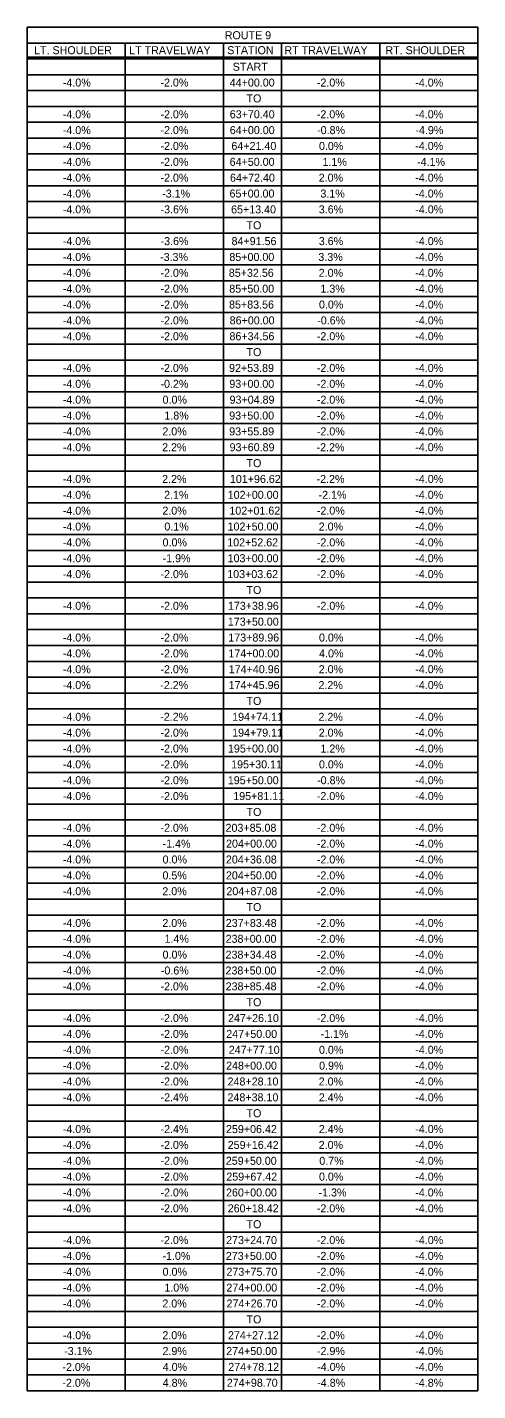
# Model space of a CAD drawing. Extents: x -15318841 to 1762012, y 465773 to 3693661.
# Drawn here: x -15318841 to -15318672, y 3691464 to 3691975 of the extents above; entities that cross this region are included whole.
import ezdxf

# ---------------------------------------------------------------- set-up
doc = ezdxf.new("R2010")
doc.units = 0
doc.layers.add('BORDER', color=7, linetype='Continuous')
doc.layers.add('DIMENSIONS', color=7, linetype='Continuous')

msp = doc.modelspace()

# ---------------------------------------------------------------- linework, layer by layer
at = {"layer": 'BORDER'}
for p, q in [((-15318803.96, 3691969.22), (-15318803.96, 3691464.16)), ((-15318767.19, 3691969.22), (-15318767.19, 3691464.16)), ((-15318745.32, 3691969.22), (-15318745.32, 3691464.16)), ((-15318708.55, 3691969.22), (-15318708.55, 3691464.16)), ((-15318840.73, 3691963.94), (-15318671.78, 3691963.94)), ((-15318840.73, 3691963.35), (-15318671.78, 3691963.35)), ((-15318840.73, 3691957.4), (-15318671.78, 3691957.4)), ((-15318840.73, 3691957.4), (-15318671.78, 3691957.4)), ((-15318840.73, 3691957.4), (-15318671.78, 3691957.4)), ((-15318840.73, 3691951.46), (-15318671.78, 3691951.46)), ((-15318840.73, 3691945.52), (-15318671.78, 3691945.52)), ((-15318840.73, 3691939.58), (-15318671.78, 3691939.58)), ((-15318840.73, 3691933.63), (-15318671.78, 3691933.63)), ((-15318840.73, 3691927.69), (-15318671.78, 3691927.69)), ((-15318840.73, 3691921.75), (-15318671.78, 3691921.75)), ((-15318840.73, 3691915.8), (-15318671.78, 3691915.8)), ((-15318840.73, 3691909.86), (-15318671.78, 3691909.86)), ((-15318840.73, 3691903.92), (-15318671.78, 3691903.92)), ((-15318840.73, 3691897.98), (-15318671.78, 3691897.98)), ((-15318840.73, 3691892.03), (-15318671.78, 3691892.03)), ((-15318840.73, 3691886.09), (-15318671.78, 3691886.09)), ((-15318840.73, 3691880.15), (-15318671.78, 3691880.15)), ((-15318840.73, 3691874.21), (-15318671.78, 3691874.21)), ((-15318840.73, 3691868.26), (-15318671.78, 3691868.26)), ((-15318840.73, 3691862.32), (-15318671.78, 3691862.32)), ((-15318840.73, 3691856.38), (-15318671.78, 3691856.38)), ((-15318840.73, 3691850.43), (-15318671.78, 3691850.43)), ((-15318840.73, 3691844.49), (-15318671.78, 3691844.49)), ((-15318840.73, 3691838.55), (-15318671.78, 3691838.55)), ((-15318840.73, 3691832.61), (-15318671.78, 3691832.61)), ((-15318840.73, 3691826.66), (-15318671.78, 3691826.66)), ((-15318840.73, 3691820.72), (-15318671.78, 3691820.72)), ((-15318840.73, 3691814.78), (-15318671.78, 3691814.78)), ((-15318840.73, 3691808.84), (-15318671.78, 3691808.84)), ((-15318840.73, 3691802.89), (-15318671.78, 3691802.89)), ((-15318840.73, 3691796.95), (-15318671.78, 3691796.95)), ((-15318840.73, 3691791.01), (-15318671.78, 3691791.01)), ((-15318840.73, 3691785.07), (-15318671.78, 3691785.07)), ((-15318840.73, 3691779.12), (-15318671.78, 3691779.12)), ((-15318840.73, 3691773.18), (-15318671.78, 3691773.18)), ((-15318840.73, 3691767.24), (-15318671.78, 3691767.24)), ((-15318840.73, 3691761.29), (-15318671.78, 3691761.29)), ((-15318840.73, 3691755.35), (-15318671.78, 3691755.35)), ((-15318840.73, 3691749.41), (-15318671.78, 3691749.41)), ((-15318840.73, 3691743.47), (-15318671.78, 3691743.47)), ((-15318840.73, 3691737.52), (-15318671.78, 3691737.52)), ((-15318840.73, 3691731.58), (-15318671.78, 3691731.58)), ((-15318840.73, 3691725.64), (-15318671.78, 3691725.64)), ((-15318840.73, 3691719.7), (-15318671.78, 3691719.7)), ((-15318840.73, 3691713.75), (-15318671.78, 3691713.75)), ((-15318840.73, 3691707.81), (-15318671.78, 3691707.81)), ((-15318840.73, 3691701.87), (-15318671.78, 3691701.87)), ((-15318840.73, 3691695.92), (-15318671.78, 3691695.92)), ((-15318840.73, 3691689.98), (-15318671.78, 3691689.98)), ((-15318840.73, 3691684.04), (-15318671.78, 3691684.04)), ((-15318840.73, 3691678.1), (-15318671.78, 3691678.1)), ((-15318840.73, 3691672.15), (-15318671.78, 3691672.15)), ((-15318840.73, 3691666.21), (-15318671.78, 3691666.21)), ((-15318840.73, 3691660.27), (-15318671.78, 3691660.27)), ((-15318840.73, 3691654.33), (-15318671.78, 3691654.33)), ((-15318840.73, 3691648.38), (-15318671.78, 3691648.38)), ((-15318840.73, 3691642.44), (-15318671.78, 3691642.44)), ((-15318840.73, 3691636.5), (-15318671.78, 3691636.5)), ((-15318840.73, 3691630.55), (-15318671.78, 3691630.55)), ((-15318840.73, 3691624.61), (-15318671.78, 3691624.61)), ((-15318840.73, 3691618.67), (-15318671.78, 3691618.67)), ((-15318840.73, 3691612.73), (-15318671.78, 3691612.73)), ((-15318840.73, 3691606.78), (-15318671.78, 3691606.78)), ((-15318840.73, 3691600.84), (-15318671.78, 3691600.84)), ((-15318840.73, 3691594.9), (-15318671.78, 3691594.9)), ((-15318840.73, 3691588.96), (-15318671.78, 3691588.96)), ((-15318840.73, 3691583.01), (-15318671.78, 3691583.01)), ((-15318840.73, 3691577.07), (-15318671.78, 3691577.07)), ((-15318840.73, 3691571.13), (-15318671.78, 3691571.13)), ((-15318840.73, 3691565.19), (-15318671.78, 3691565.19)), ((-15318840.73, 3691559.24), (-15318671.78, 3691559.24)), ((-15318840.73, 3691553.3), (-15318671.78, 3691553.3)), ((-15318840.73, 3691547.36), (-15318671.78, 3691547.36)), ((-15318840.73, 3691541.41), (-15318671.78, 3691541.41)), ((-15318840.73, 3691535.47), (-15318671.78, 3691535.47)), ((-15318840.73, 3691529.53), (-15318671.78, 3691529.53)), ((-15318840.73, 3691523.59), (-15318671.78, 3691523.59)), ((-15318840.73, 3691517.64), (-15318671.78, 3691517.64)), ((-15318840.73, 3691511.7), (-15318671.78, 3691511.7)), ((-15318840.73, 3691505.76), (-15318671.78, 3691505.76)), ((-15318840.73, 3691499.82), (-15318671.78, 3691499.82)), ((-15318840.73, 3691493.87), (-15318671.78, 3691493.87)), ((-15318840.73, 3691487.93), (-15318671.78, 3691487.93)), ((-15318840.73, 3691481.99), (-15318671.78, 3691481.99)), ((-15318840.73, 3691476.04), (-15318671.78, 3691476.04)), ((-15318840.73, 3691470.1), (-15318671.78, 3691470.1))]:
    msp.add_line(p, q, dxfattribs=at)
msp.add_lwpolyline([(-15318840.73, 3691969.22), (-15318840.73, 3691975.17), (-15318671.78, 3691975.17), (-15318671.78, 3691969.22)], dxfattribs=at)
msp.add_lwpolyline([(-15318840.73, 3691969.22), (-15318671.78, 3691969.22), (-15318671.78, 3691464.16), (-15318840.73, 3691464.16)], close=True, dxfattribs=at)

# ---------------------------------------------------------------- texts
at = {"layer": 'DIMENSIONS'}
for s, p in [('ROUTE 9', (-15318766.66, 3691970.69)), ('LT. SHOULDER', (-15318838.17, 3691965.08)), ('LT TRAVELWAY', (-15318802.51, 3691965.08)), ('STATION', (-15318765.73, 3691965.08)), ('RT TRAVELWAY', (-15318744.29, 3691965.08)), ('RT. SHOULDER', (-15318706.42, 3691965.08)), ('START', (-15318763.65, 3691958.86)), ('-4.0%', (-15318827.39, 3691952.95)), ('-2.0%', (-15318790.77, 3691952.95)), ('44+00.00', (-15318764.78, 3691952.95)), ('-2.0%', (-15318732.12, 3691952.95)), ('-4.0%', (-15318695.21, 3691952.95)), ('TO', (-15318758.49, 3691947.01)), ('-4.0%', (-15318827.39, 3691941.06)), ('-2.0%', (-15318790.77, 3691941.06)), ('63+70.40', (-15318764.78, 3691941.06)), ('-2.0%', (-15318732.12, 3691941.06)), ('-4.0%', (-15318695.21, 3691941.06)), ('-4.0%', (-15318827.39, 3691935.12)), ('-2.0%', (-15318790.77, 3691935.12)), ('64+00.00', (-15318764.78, 3691935.12)), ('-0.8%', (-15318732.03, 3691935.12)), ('-4.9%', (-15318695.17, 3691935.12)), ('-4.0%', (-15318827.39, 3691929.18)), ('-2.0%', (-15318790.77, 3691929.18)), ('64+21.40', (-15318764.16, 3691929.18)), ('0.0%', (-15318731.32, 3691929.18)), ('-4.0%', (-15318695.21, 3691929.18)), ('-4.0%', (-15318827.39, 3691923.23)), ('-2.0%', (-15318790.77, 3691923.23)), ('64+50.00', (-15318764.82, 3691923.23)), ('1.1%', (-15318730, 3691923.23)), ('-4.1%', (-15318694.55, 3691923.23)), ('-4.0%', (-15318827.39, 3691917.29)), ('-2.0%', (-15318790.77, 3691917.29)), ('64+72.40', (-15318764.7, 3691917.29)), ('2.0%', (-15318731.42, 3691917.29)), ('-4.0%', (-15318695.21, 3691917.29)), ('-4.0%', (-15318827.39, 3691911.35)), ('-3.1%', (-15318790.13, 3691911.35)), ('65+00.00', (-15318764.87, 3691911.35)), ('3.1%', (-15318730.78, 3691911.35)), ('-4.0%', (-15318695.21, 3691911.35)), ('-4.0%', (-15318827.39, 3691905.41)), ('-3.6%', (-15318790.74, 3691905.41)), ('65+13.40', (-15318764.28, 3691905.41)), ('3.6%', (-15318731.39, 3691905.41)), ('-4.0%', (-15318695.21, 3691905.41)), ('TO', (-15318758.49, 3691899.46)), ('-4.0%', (-15318827.39, 3691893.52)), ('-3.6%', (-15318790.74, 3691893.52)), ('84+91.56', (-15318764.11, 3691893.52)), ('3.6%', (-15318731.39, 3691893.52)), ('-4.0%', (-15318695.21, 3691893.52)), ('-4.0%', (-15318827.39, 3691887.58)), ('-3.3%', (-15318790.91, 3691887.58)), ('85+00.00', (-15318764.92, 3691887.58)), ('3.3%', (-15318731.56, 3691887.58)), ('-4.0%', (-15318695.21, 3691887.58)), ('-4.0%', (-15318827.39, 3691881.64)), ('-2.0%', (-15318790.77, 3691881.64)), ('85+32.56', (-15318765.13, 3691881.64)), ('2.0%', (-15318731.42, 3691881.64)), ('-4.0%', (-15318695.21, 3691881.64)), ('-4.0%', (-15318827.39, 3691875.69)), ('-2.0%', (-15318790.77, 3691875.69)), ('85+50.00', (-15318764.97, 3691875.69)), ('1.3%', (-15318730.78, 3691875.69)), ('-4.0%', (-15318695.21, 3691875.69)), ('-4.0%', (-15318827.39, 3691869.75)), ('-2.0%', (-15318790.77, 3691869.75)), ('85+83.56', (-15318765.04, 3691869.75)), ('0.0%', (-15318731.32, 3691869.75)), ('-4.0%', (-15318695.21, 3691869.75)), ('-4.0%', (-15318827.39, 3691863.81)), ('-2.0%', (-15318790.77, 3691863.81)), ('86+00.00', (-15318764.82, 3691863.81)), ('-0.6%', (-15318731.98, 3691863.81)), ('-4.0%', (-15318695.21, 3691863.81)), ('-4.0%', (-15318827.39, 3691857.87)), ('-2.0%', (-15318790.77, 3691857.87)), ('86+34.56', (-15318764.89, 3691857.87)), ('-2.0%', (-15318732.12, 3691857.87)), ('-4.0%', (-15318695.21, 3691857.87)), ('TO', (-15318758.49, 3691851.92)), ('-4.0%', (-15318827.39, 3691845.98)), ('-2.0%', (-15318790.77, 3691845.98)), ('92+53.89', (-15318765.04, 3691845.98)), ('-2.0%', (-15318732.12, 3691845.98)), ('-4.0%', (-15318695.21, 3691845.98)), ('-4.0%', (-15318827.39, 3691840.04)), ('-0.2%', (-15318790.77, 3691840.04)), ('93+00.00', (-15318764.94, 3691840.04)), ('-2.0%', (-15318732.12, 3691840.04)), ('-4.0%', (-15318695.21, 3691840.04)), ('-4.0%', (-15318827.39, 3691834.09)), ('0.0%', (-15318789.97, 3691834.09)), ('93+04.89', (-15318764.85, 3691834.09)), ('-2.0%', (-15318732.12, 3691834.09)), ('-4.0%', (-15318695.21, 3691834.09)), ('-4.0%', (-15318827.39, 3691828.15)), ('1.8%', (-15318789.3, 3691828.15)), ('93+50.00', (-15318764.99, 3691828.15)), ('-2.0%', (-15318732.12, 3691828.15)), ('-4.0%', (-15318695.21, 3691828.15)), ('-4.0%', (-15318827.39, 3691822.21)), ('2.0%', (-15318790.06, 3691822.21)), ('93+55.89', (-15318764.99, 3691822.21)), ('-2.0%', (-15318732.12, 3691822.21)), ('-4.0%', (-15318695.21, 3691822.21)), ('-4.0%', (-15318827.39, 3691816.27)), ('2.2%', (-15318790.15, 3691816.27)), ('93+60.89', (-15318764.85, 3691816.27)), ('-2.2%', (-15318732.22, 3691816.27)), ('-4.0%', (-15318695.21, 3691816.27)), ('TO', (-15318758.49, 3691810.32)), ('-4.0%', (-15318827.39, 3691804.38)), ('2.2%', (-15318790.15, 3691804.38)), ('101+96.62', (-15318764.74, 3691804.38)), ('-2.2%', (-15318732.22, 3691804.38)), ('-4.0%', (-15318695.21, 3691804.38)), ('-4.0%', (-15318827.39, 3691798.44)), ('2.1%', (-15318789.4, 3691798.44)), ('102+00.00', (-15318765.55, 3691798.44)), ('-2.1%', (-15318731.46, 3691798.44)), ('-4.0%', (-15318695.21, 3691798.44)), ('-4.0%', (-15318827.39, 3691792.5)), ('2.0%', (-15318790.06, 3691792.5)), ('102+01.62', (-15318764.93, 3691792.5)), ('-2.0%', (-15318732.12, 3691792.5)), ('-4.0%', (-15318695.21, 3691792.5)), ('-4.0%', (-15318827.39, 3691786.55)), ('0.1%', (-15318789.3, 3691786.55)), ('102+50.00', (-15318765.6, 3691786.55)), ('2.0%', (-15318731.42, 3691786.55)), ('-4.0%', (-15318695.21, 3691786.55)), ('-4.0%', (-15318827.39, 3691780.61)), ('0.0%', (-15318789.97, 3691780.61)), ('102+52.62', (-15318765.73, 3691780.61)), ('-2.0%', (-15318732.12, 3691780.61)), ('-4.0%', (-15318695.21, 3691780.61)), ('-4.0%', (-15318827.39, 3691774.67)), ('-1.9%', (-15318789.96, 3691774.67)), ('103+00.00', (-15318765.58, 3691774.67)), ('-2.0%', (-15318732.12, 3691774.67)), ('-4.0%', (-15318695.21, 3691774.67)), ('-4.0%', (-15318827.39, 3691768.72)), ('-2.0%', (-15318790.77, 3691768.72)), ('103+03.62', (-15318765.73, 3691768.72)), ('-2.0%', (-15318732.12, 3691768.72)), ('-4.0%', (-15318695.21, 3691768.72)), ('TO', (-15318758.49, 3691762.78)), ('-4.0%', (-15318827.39, 3691756.84)), ('-2.0%', (-15318790.77, 3691756.84)), ('173+38.96', (-15318765.48, 3691756.84)), ('-2.0%', (-15318732.12, 3691756.84)), ('-4.0%', (-15318695.21, 3691756.84)), ('173+50.00', (-15318765.51, 3691750.9)), ('-4.0%', (-15318827.39, 3691744.95)), ('-2.0%', (-15318790.77, 3691744.95)), ('173+89.96', (-15318765.32, 3691744.95)), ('0.0%', (-15318731.32, 3691744.95)), ('-4.0%', (-15318695.21, 3691744.95)), ('-4.0%', (-15318827.39, 3691739.01)), ('-2.0%', (-15318790.77, 3691739.01)), ('174+00.00', (-15318765.3, 3691739.01)), ('4.0%', (-15318731.27, 3691739.01)), ('-4.0%', (-15318695.21, 3691739.01)), ('-4.0%', (-15318827.39, 3691733.07)), ('-2.0%', (-15318790.77, 3691733.07)), ('174+40.96', (-15318765.15, 3691733.07)), ('2.0%', (-15318731.42, 3691733.07)), ('-4.0%', (-15318695.21, 3691733.07)), ('-4.0%', (-15318827.39, 3691727.13)), ('-2.2%', (-15318790.86, 3691727.13)), ('174+45.96', (-15318765.2, 3691727.13)), ('2.2%', (-15318731.51, 3691727.13)), ('-4.0%', (-15318695.21, 3691727.13)), ('TO', (-15318758.49, 3691721.18)), ('-4.0%', (-15318827.39, 3691715.24)), ('-2.2%', (-15318790.86, 3691715.24)), ('194+74.11', (-15318763.88, 3691715.24)), ('2.2%', (-15318731.51, 3691715.24)), ('-4.0%', (-15318695.21, 3691715.24)), ('-4.0%', (-15318827.39, 3691709.3)), ('-2.0%', (-15318790.77, 3691709.3)), ('194+79.11', (-15318763.88, 3691709.3)), ('2.0%', (-15318731.42, 3691709.3)), ('-4.0%', (-15318695.21, 3691709.3)), ('-4.0%', (-15318827.39, 3691703.35)), ('-2.0%', (-15318790.77, 3691703.35)), ('195+00.00', (-15318765.46, 3691703.35)), ('1.2%', (-15318730.76, 3691703.35)), ('-4.0%', (-15318695.21, 3691703.35)), ('-4.0%', (-15318827.39, 3691697.41)), ('-2.0%', (-15318790.77, 3691697.41)), ('195+30.11', (-15318764.26, 3691697.41)), ('0.0%', (-15318731.32, 3691697.41)), ('-4.0%', (-15318695.21, 3691697.41)), ('-4.0%', (-15318827.39, 3691691.47)), ('-2.0%', (-15318790.77, 3691691.47)), ('195+50.00', (-15318765.51, 3691691.47)), ('-0.8%', (-15318732.03, 3691691.47)), ('-4.0%', (-15318695.21, 3691691.47)), ('-4.0%', (-15318827.39, 3691685.53)), ('-2.0%', (-15318790.77, 3691685.53)), ('195+81.11', (-15318763.48, 3691685.53)), ('-2.0%', (-15318732.12, 3691685.53)), ('-4.0%', (-15318695.21, 3691685.53)), ('TO', (-15318758.49, 3691679.58)), ('-4.0%', (-15318827.39, 3691673.64)), ('-2.0%', (-15318790.77, 3691673.64)), ('203+85.08', (-15318766.37, 3691673.64)), ('-2.0%', (-15318732.12, 3691673.64)), ('-4.0%', (-15318695.21, 3691673.64)), ('-4.0%', (-15318827.39, 3691667.7)), ('-1.4%', (-15318789.96, 3691667.7)), ('204+00.00', (-15318766.17, 3691667.7)), ('-2.0%', (-15318732.12, 3691667.7)), ('-4.0%', (-15318695.21, 3691667.7)), ('-4.0%', (-15318827.39, 3691661.76)), ('0.0%', (-15318789.97, 3691661.76)), ('204+36.08', (-15318766.23, 3691661.76)), ('-2.0%', (-15318732.12, 3691661.76)), ('-4.0%', (-15318695.21, 3691661.76)), ('-4.0%', (-15318827.39, 3691655.81)), ('0.5%', (-15318790.01, 3691655.81)), ('204+50.00', (-15318766.22, 3691655.81)), ('-2.0%', (-15318732.12, 3691655.81)), ('-4.0%', (-15318695.21, 3691655.81)), ('-4.0%', (-15318827.39, 3691649.87)), ('2.0%', (-15318790.06, 3691649.87)), ('204+87.08', (-15318766.04, 3691649.87)), ('-2.0%', (-15318732.12, 3691649.87)), ('-4.0%', (-15318695.21, 3691649.87)), ('TO', (-15318758.49, 3691643.93)), ('-4.0%', (-15318827.39, 3691637.98)), ('2.0%', (-15318790.06, 3691637.98)), ('237+83.48', (-15318766.28, 3691637.98)), ('-2.0%', (-15318732.12, 3691637.98)), ('-4.0%', (-15318695.21, 3691637.98)), ('-4.0%', (-15318827.39, 3691632.04)), ('1.4%', (-15318789.26, 3691632.04)), ('238+00.00', (-15318766.33, 3691632.04)), ('-2.0%', (-15318732.12, 3691632.04)), ('-4.0%', (-15318695.21, 3691632.04)), ('-4.0%', (-15318827.39, 3691626.1)), ('0.0%', (-15318789.97, 3691626.1)), ('238+34.48', (-15318766.35, 3691626.1)), ('-2.0%', (-15318732.12, 3691626.1)), ('-4.0%', (-15318695.21, 3691626.1)), ('-4.0%', (-15318827.39, 3691620.16)), ('-0.6%', (-15318790.63, 3691620.16)), ('238+50.00', (-15318766.38, 3691620.16)), ('-2.0%', (-15318732.12, 3691620.16)), ('-4.0%', (-15318695.21, 3691620.16)), ('-4.0%', (-15318827.39, 3691614.21)), ('-2.0%', (-15318790.77, 3691614.21)), ('238+85.48', (-15318766.32, 3691614.21)), ('-2.0%', (-15318732.12, 3691614.21)), ('-4.0%', (-15318695.21, 3691614.21)), ('TO', (-15318758.49, 3691608.27)), ('-4.0%', (-15318827.39, 3691602.33)), ('-2.0%', (-15318790.77, 3691602.33)), ('247+26.10', (-15318765.44, 3691602.33)), ('-2.0%', (-15318732.12, 3691602.33)), ('-4.0%', (-15318695.21, 3691602.33)), ('-4.0%', (-15318827.39, 3691596.39)), ('-2.0%', (-15318790.77, 3691596.39)), ('247+50.00', (-15318766.1, 3691596.39)), ('-1.1%', (-15318730.71, 3691596.39)), ('-4.0%', (-15318695.21, 3691596.39)), ('-4.0%', (-15318827.39, 3691590.44)), ('-2.0%', (-15318790.77, 3691590.44)), ('247+77.10', (-15318765.15, 3691590.44)), ('0.0%', (-15318731.32, 3691590.44)), ('-4.0%', (-15318695.21, 3691590.44)), ('-4.0%', (-15318827.39, 3691584.5)), ('-2.0%', (-15318790.77, 3691584.5)), ('248+00.00', (-15318766.17, 3691584.5)), ('0.9%', (-15318731.27, 3691584.5)), ('-4.0%', (-15318695.21, 3691584.5)), ('-4.0%', (-15318827.39, 3691578.56)), ('-2.0%', (-15318790.77, 3691578.56)), ('248+28.10', (-15318765.6, 3691578.56)), ('2.0%', (-15318731.42, 3691578.56)), ('-4.0%', (-15318695.21, 3691578.56)), ('-4.0%', (-15318827.39, 3691572.62)), ('-2.4%', (-15318790.72, 3691572.62)), ('248+38.10', (-15318765.63, 3691572.62)), ('2.4%', (-15318731.37, 3691572.62)), ('-4.0%', (-15318695.21, 3691572.62)), ('TO', (-15318758.49, 3691566.67)), ('-4.0%', (-15318827.39, 3691560.73)), ('-2.4%', (-15318790.72, 3691560.73)), ('259+06.42', (-15318766.2, 3691560.73)), ('2.4%', (-15318731.37, 3691560.73)), ('-4.0%', (-15318695.21, 3691560.73)), ('-4.0%', (-15318827.39, 3691554.79)), ('-2.0%', (-15318790.77, 3691554.79)), ('259+16.42', (-15318765.54, 3691554.79)), ('2.0%', (-15318731.42, 3691554.79)), ('-4.0%', (-15318695.21, 3691554.79)), ('-4.0%', (-15318827.39, 3691548.84)), ('-2.0%', (-15318790.77, 3691548.84)), ('259+50.00', (-15318766.26, 3691548.84)), ('0.7%', (-15318731.2, 3691548.84)), ('-4.0%', (-15318695.21, 3691548.84)), ('-4.0%', (-15318827.39, 3691542.9)), ('-2.0%', (-15318790.77, 3691542.9)), ('259+67.42', (-15318766.09, 3691542.9)), ('0.0%', (-15318731.32, 3691542.9)), ('-4.0%', (-15318695.21, 3691542.9)), ('-4.0%', (-15318827.39, 3691536.96)), ('-2.0%', (-15318790.77, 3691536.96)), ('260+00.00', (-15318766.17, 3691536.96)), ('-1.3%', (-15318731.49, 3691536.96)), ('-4.0%', (-15318695.21, 3691536.96)), ('-4.0%', (-15318827.39, 3691531.02)), ('-2.0%', (-15318790.77, 3691531.02)), ('260+18.42', (-15318765.54, 3691531.02)), ('-2.0%', (-15318732.12, 3691531.02)), ('-4.0%', (-15318695.21, 3691531.02)), ('TO', (-15318758.49, 3691525.07)), ('-4.0%', (-15318827.39, 3691519.13)), ('-2.0%', (-15318790.77, 3691519.13)), ('273+24.70', (-15318766.15, 3691519.13)), ('-2.0%', (-15318732.12, 3691519.13)), ('-4.0%', (-15318695.21, 3691519.13)), ('-4.0%', (-15318827.39, 3691513.19)), ('-1.0%', (-15318790.01, 3691513.19)), ('273+50.00', (-15318766.26, 3691513.19)), ('-2.0%', (-15318732.12, 3691513.19)), ('-4.0%', (-15318695.21, 3691513.19)), ('-4.0%', (-15318827.39, 3691507.25)), ('0.0%', (-15318789.97, 3691507.25)), ('273+75.70', (-15318766.03, 3691507.25)), ('-2.0%', (-15318732.12, 3691507.25)), ('-4.0%', (-15318695.21, 3691507.25)), ('-4.0%', (-15318827.39, 3691501.3)), ('1.0%', (-15318789.3, 3691501.3)), ('274+00.00', (-15318766.05, 3691501.3)), ('-2.0%', (-15318732.12, 3691501.3)), ('-4.0%', (-15318695.21, 3691501.3)), ('-4.0%', (-15318827.39, 3691495.36)), ('2.0%', (-15318790.06, 3691495.36)), ('274+26.70', (-15318765.98, 3691495.36)), ('-2.0%', (-15318732.12, 3691495.36)), ('-4.0%', (-15318695.21, 3691495.36)), ('TO', (-15318758.49, 3691489.42)), ('-4.0%', (-15318827.39, 3691483.47)), ('2.0%', (-15318790.06, 3691483.47)), ('274+27.12', (-15318765.45, 3691483.47)), ('-2.0%', (-15318732.12, 3691483.47)), ('-4.0%', (-15318695.21, 3691483.47)), ('-3.1%', (-15318826.9, 3691477.53)), ('2.9%', (-15318790.01, 3691477.53)), ('274+50.00', (-15318766.1, 3691477.53)), ('-2.9%', (-15318732.08, 3691477.53)), ('-4.0%', (-15318695.21, 3691477.53)), ('-2.0%', (-15318827.54, 3691471.59)), ('4.0%', (-15318789.92, 3691471.59)), ('274+78.12', (-15318765.35, 3691471.59)), ('-4.0%', (-15318731.98, 3691471.59)), ('-4.0%', (-15318695.21, 3691471.59)), ('-2.0%', (-15318827.54, 3691465.65)), ('4.8%', (-15318789.92, 3691465.65)), ('274+98.70', (-15318765.89, 3691465.65)), ('-4.8%', (-15318731.98, 3691465.65)), ('-4.8%', (-15318695.21, 3691465.65))]:
    msp.add_text(s, height=3, dxfattribs=at).set_placement(p)

doc.saveas('drawing.dxf')
